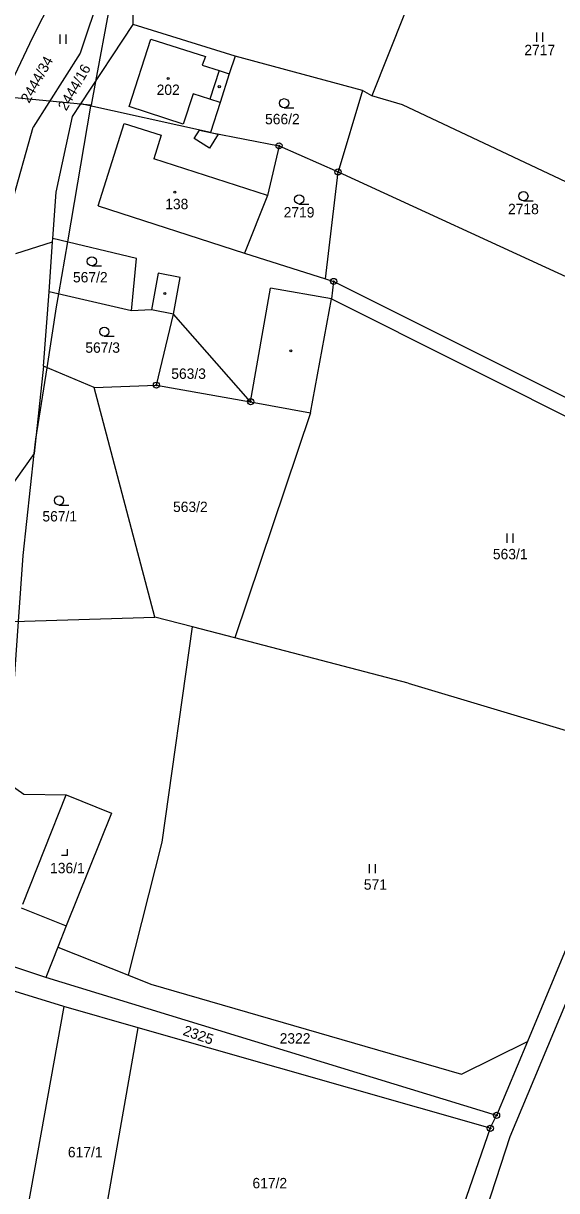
# Model space of a CAD drawing. Extents: x -546762 to -540209, y -1046851 to -1035694.
# Drawn here: x -542556.7 to -542469.1, y -1039468.6 to -1039277.1 of the extents above; entities that cross this region are included whole.
import ezdxf

# ---------------------------------------------------------------- set-up
doc = ezdxf.new("R2010")
doc.units = 0
for name, color, linetype in [('Vrstva 1', 7, 'Continuous'), ('Vrstva 18', 7, 'Continuous'), ('Vrstva 19', 7, 'Continuous'), ('Vrstva 24', 7, 'Continuous'), ('Vrstva 25', 7, 'Continuous'), ('Vrstva 3', 7, 'Continuous'), ('Vrstva 30', 7, 'Continuous'), ('Vrstva 37', 7, 'Continuous'), ('Vrstva 4', 7, 'Continuous'), ('Vrstva 52', 7, 'Continuous')]:
    doc.layers.add(name, color=color, linetype=linetype)

msp = doc.modelspace()

# ---------------------------------------------------------------- linework, layer by layer
at = {"layer": 'Vrstva 1'}
for p, q in [((-542501, -1039288.13), (-542521.91, -1039282.5)), ((-542525.96, -1039295.03), (-542514.67, -1039297.22)), ((-542509.5, -1039341.02), (-542506.07, -1039322.32)), ((-542493.48, -1039385.34), (-542454.3, -1039397.07)), ((-542484.72, -1039449.49), (-542473.9, -1039444.11))]:
    msp.add_line(p, q, dxfattribs=at)
for points in [[(-542538.66, -1039277.31), (-542539.01, -1039251.37)], [(-542486.14, -1039255.6), (-542499.44, -1039289.01)], [(-542555.14, -1039279.37), (-542545.45, -1039260.3)], [(-542543.97, -1039271.83), (-542547.35, -1039282.02)], [(-542547.23, -1039290.34), (-542538.66, -1039277.31)], [(-542521.91, -1039282.5), (-542538.66, -1039277.31)], [(-542569.04, -1039308.59), (-542555.14, -1039279.37)], [(-542547.35, -1039282.02), (-542555.06, -1039294.18)], [(-542521.91, -1039282.5), (-542522.85, -1039285.41)], [(-542522.85, -1039285.41), (-542524.37, -1039290.12)], [(-542501, -1039288.13), (-542505, -1039301.49)], [(-542499.44, -1039289.01), (-542501, -1039288.13)], [(-542524.37, -1039290.12), (-542525.96, -1039295.03)], [(-542494.43, -1039290.51), (-542499.44, -1039289.01)], [(-542548.58, -1039292.39), (-542547.23, -1039290.34)], [(-542525.96, -1039295.03), (-542547.23, -1039290.34)], [(-542460.86, -1039306.3), (-542494.43, -1039290.51)], [(-542551.27, -1039304.84), (-542548.58, -1039292.39)], [(-542558.59, -1039306.85), (-542555.06, -1039294.18)], [(-542514.67, -1039297.22), (-542516.6, -1039305.34)], [(-542514.67, -1039297.22), (-542505, -1039301.49)], [(-542507.04, -1039319.03), (-542505, -1039301.49)], [(-542505, -1039301.49), (-542466.18, -1039319.31)], [(-542551.82, -1039312.41), (-542551.27, -1039304.84)], [(-542516.6, -1039305.34), (-542520.35, -1039314.81)], [(-542557.91, -1039314.9), (-542551.86, -1039312.96)], [(-542552.45, -1039321.14), (-542551.86, -1039312.96)], [(-542551.86, -1039312.96), (-542551.82, -1039312.41)], [(-542538.1, -1039315.69), (-542551.82, -1039312.41)], [(-542520.35, -1039314.81), (-542507.04, -1039319.03)], [(-542538.9, -1039324.26), (-542538.1, -1039315.69)], [(-542507.04, -1039319.03), (-542505.72, -1039319.46)], [(-542505.72, -1039319.46), (-542506.07, -1039322.32)], [(-542461.17, -1039341.73), (-542505.72, -1039319.46)], [(-542553.34, -1039333.38), (-542552.45, -1039321.14)], [(-542538.9, -1039324.26), (-542552.45, -1039321.14)], [(-542506.07, -1039322.32), (-542462.28, -1039344.21)], [(-542535.6, -1039324.14), (-542538.9, -1039324.26)], [(-542531.99, -1039324.82), (-542535.6, -1039324.14)], [(-542534.82, -1039336.47), (-542531.99, -1039324.82)], [(-542519.35, -1039339.2), (-542531.99, -1039324.82)], [(-542553.34, -1039333.38), (-542554.88, -1039347.66)], [(-542545.03, -1039336.86), (-542553.34, -1039333.38)], [(-542545.03, -1039336.86), (-542534.82, -1039336.47)], [(-542535.06, -1039374.51), (-542545.03, -1039336.86)], [(-542534.82, -1039336.47), (-542519.35, -1039339.2)], [(-542519.35, -1039339.2), (-542509.5, -1039341.02)], [(-542509.5, -1039341.02), (-542521.93, -1039377.93)], [(-542554.88, -1039347.66), (-542574.3, -1039374.91)], [(-542572.62, -1039375.69), (-542535.06, -1039374.51)], [(-542528.9, -1039376.11), (-542535.06, -1039374.51)], [(-542533.9, -1039411.45), (-542528.9, -1039376.11)], [(-542521.93, -1039377.93), (-542528.9, -1039376.11)], [(-542493.48, -1039385.34), (-542521.93, -1039377.93)], [(-542454.3, -1039397.07), (-542473.9, -1039444.11)], [(-542476.73, -1039459.71), (-542451.27, -1039398.94)], [(-542562.27, -1039399.57), (-542556.57, -1039403.53)], [(-542556.57, -1039403.53), (-542549.62, -1039403.69)], [(-542549.62, -1039403.69), (-542542.21, -1039406.65)], [(-542542.21, -1039406.65), (-542549.62, -1039425.17)], [(-542539.39, -1039433.27), (-542533.9, -1039411.45)], [(-542557.02, -1039422.21), (-542549.62, -1039425.17)], [(-542549.62, -1039425.17), (-542551, -1039428.63)], [(-542551, -1039428.63), (-542553, -1039433.61)], [(-542551, -1039428.63), (-542539.39, -1039433.27)], [(-542553, -1039433.61), (-542558.25, -1039431.87)], [(-542478.96, -1039456.24), (-542553, -1039433.61)], [(-542539.39, -1039433.27), (-542535.72, -1039434.74)], [(-542550, -1039438.39), (-542558.73, -1039435.72)], [(-542535.72, -1039434.74), (-542484.72, -1039449.49)], [(-542550, -1039438.39), (-542557.58, -1039480.26)], [(-542537.82, -1039441.87), (-542550, -1039438.39)], [(-542545.2, -1039483.83), (-542537.82, -1039441.87)], [(-542479.99, -1039458.36), (-542537.82, -1039441.87)], [(-542473.9, -1039444.11), (-542478.96, -1039456.24)], [(-542479.99, -1039458.36), (-542478.96, -1039456.24)], [(-542479.99, -1039458.36), (-542494.25, -1039499.38)], [(-542490.7, -1039502.54), (-542476.73, -1039459.71)]]:
    msp.add_lwpolyline(points, dxfattribs=at)
at = {"layer": 'Vrstva 24'}
for centre, radius in [((-542514.67, -1039297.22), 0.5), ((-542514.67, -1039297.22), 0.1), ((-542505, -1039301.49), 0.5), ((-542505, -1039301.49), 0.1), ((-542505.72, -1039319.46), 0.5), ((-542505.72, -1039319.46), 0.1), ((-542534.82, -1039336.47), 0.5), ((-542534.82, -1039336.47), 0.1), ((-542519.35, -1039339.2), 0.5), ((-542519.35, -1039339.2), 0.1), ((-542478.96, -1039456.24), 0.5), ((-542478.96, -1039456.24), 0.1), ((-542479.99, -1039458.36), 0.5), ((-542479.99, -1039458.36), 0.1)]:
    msp.add_circle(centre, radius, dxfattribs=at)
at = {"layer": 'Vrstva 25'}
for p, q in [((-542472.37, -1039280.14), (-542472.37, -1039278.64)), ((-542471.37, -1039280.14), (-542471.37, -1039278.64)), ((-542550.65, -1039280.47), (-542550.65, -1039278.97)), ((-542549.65, -1039280.47), (-542549.65, -1039278.97)), ((-542513.84, -1039290.98), (-542512.24, -1039290.98)), ((-542511.38, -1039306.76), (-542509.78, -1039306.76)), ((-542474.55, -1039306.22), (-542472.95, -1039306.22)), ((-542545.42, -1039316.92), (-542543.82, -1039316.92)), ((-542543.38, -1039328.46), (-542541.78, -1039328.46)), ((-542550.81, -1039356.13), (-542549.21, -1039356.13)), ((-542477.23, -1039362.33), (-542477.23, -1039360.83)), ((-542476.23, -1039362.33), (-542476.23, -1039360.83)), ((-542499.84, -1039416.53), (-542499.84, -1039415.03)), ((-542498.84, -1039416.53), (-542498.84, -1039415.03))]:
    msp.add_line(p, q, dxfattribs=at)
msp.add_lwpolyline([(-542550.43, -1039413.56), (-542549.43, -1039413.56), (-542549.43, -1039412.56)], dxfattribs=at)
for centre, radius in [((-542532.9, -1039286.17), 0.175), ((-542524.49, -1039287.51), 0.175), ((-542513.84, -1039290.23), 0.75), ((-542531.8, -1039304.81), 0.175), ((-542511.38, -1039306.01), 0.75), ((-542474.55, -1039305.47), 0.75), ((-542545.42, -1039316.17), 0.75), ((-542533.44, -1039321.45), 0.175), ((-542543.38, -1039327.71), 0.75), ((-542512.75, -1039330.83), 0.175), ((-542550.81, -1039355.38), 0.75)]:
    msp.add_circle(centre, radius, dxfattribs=at)
at = {"layer": 'Vrstva 3'}
for points in [[(-542539.3, -1039290.78), (-542535.72, -1039279.7)], [(-542535.72, -1039279.7), (-542526.78, -1039282.55)], [(-542526.78, -1039282.55), (-542527.28, -1039283.98)], [(-542527.28, -1039283.98), (-542524.52, -1039284.87)], [(-542524.52, -1039284.87), (-542526.04, -1039289.58)], [(-542528.8, -1039288.69), (-542530.4, -1039293.65)], [(-542526.04, -1039289.58), (-542528.8, -1039288.69)], [(-542530.4, -1039293.65), (-542539.3, -1039290.78)], [(-542544.41, -1039307.04), (-542540.13, -1039293.55)], [(-542540.13, -1039293.55), (-542534.03, -1039295.48)], [(-542534.03, -1039295.48), (-542535.26, -1039299.36)], [(-542516.6, -1039305.34), (-542535.26, -1039299.36)], [(-542516.6, -1039305.34), (-542520.35, -1039314.81)], [(-542544.41, -1039307.04), (-542520.35, -1039314.81)]]:
    msp.add_lwpolyline(points, dxfattribs=at)
at = {"layer": 'Vrstva 30'}
for p, q in [((-542528.64, -1039296.02), (-542527.77, -1039294.63)), ((-542527.77, -1039294.63), (-542525.96, -1039295.03)), ((-542524.66, -1039295.28), (-542526.09, -1039297.59)), ((-542525.96, -1039295.03), (-542524.66, -1039295.28)), ((-542526.09, -1039297.59), (-542528.64, -1039296.02))]:
    msp.add_line(p, q, dxfattribs=at)
at = {"layer": 'Vrstva 37'}
for centre in [(-542532.9, -1039286.17), (-542531.8, -1039304.81)]:
    msp.add_circle(centre, 0.175, dxfattribs=at)
at = {"layer": 'Vrstva 4'}
for p, q in [((-542516.6, -1039305.34), (-542535.26, -1039299.36)), ((-542506.07, -1039322.32), (-542516.08, -1039320.55))]:
    msp.add_line(p, q, dxfattribs=at)
for points in [[(-542539.3, -1039290.78), (-542535.72, -1039279.7)], [(-542535.72, -1039279.7), (-542526.78, -1039282.55)], [(-542526.78, -1039282.55), (-542527.28, -1039283.98)], [(-542527.28, -1039283.98), (-542524.52, -1039284.87)], [(-542524.52, -1039284.87), (-542526.04, -1039289.58)], [(-542524.52, -1039284.87), (-542522.85, -1039285.41)], [(-542528.8, -1039288.69), (-542530.4, -1039293.65)], [(-542526.04, -1039289.58), (-542528.8, -1039288.69)], [(-542524.37, -1039290.12), (-542526.04, -1039289.58)], [(-542530.4, -1039293.65), (-542539.3, -1039290.78)], [(-542544.41, -1039307.04), (-542540.13, -1039293.55)], [(-542540.13, -1039293.55), (-542534.03, -1039295.48)], [(-542534.03, -1039295.48), (-542535.26, -1039299.36)], [(-542544.41, -1039307.04), (-542520.35, -1039314.81)], [(-542534.52, -1039318.13), (-542535.6, -1039324.14)], [(-542530.91, -1039318.81), (-542534.52, -1039318.13)], [(-542531.99, -1039324.82), (-542530.91, -1039318.81)], [(-542519.35, -1039339.2), (-542516.08, -1039320.55)], [(-542556.78, -1039421.58), (-542549.62, -1039403.69)]]:
    msp.add_lwpolyline(points, dxfattribs=at)
at = {"layer": 'Vrstva 52'}
for points in [[(-542540.31, -1039262.57), (-542544.81, -1039286.67), (-542545.54, -1039290.55)], [(-542545.54, -1039290.55), (-542546.85, -1039290.42), (-542547.26, -1039290.38), (-542552.34, -1039289.9), (-542559.81, -1039289.18), (-542569.64, -1039288.23)], [(-542559.32, -1039476.62), (-542559.51, -1039441.98), (-542559.57, -1039431.43), (-542559.58, -1039428.76), (-542559.41, -1039421.25), (-542558.98, -1039401.86), (-542558.8, -1039393.98), (-542557.47, -1039375.21), (-542556.71, -1039364.42), (-542554.87, -1039347.66), (-542554.61, -1039345.33), (-542552.78, -1039333.61), (-542551.22, -1039323.62), (-542550.86, -1039321.51), (-542549.39, -1039312.99), (-542545.57, -1039290.71), (-542545.54, -1039290.55)]]:
    msp.add_lwpolyline(points, dxfattribs=at)

# ---------------------------------------------------------------- texts
at = {"layer": 'Vrstva 18'}
for s, p in [('2717', (-542474.4, -1039282.35)), ('566/2', (-542516.98, -1039293.68)), ('2719', (-542513.92, -1039308.97)), ('2718', (-542477.08, -1039308.43)), ('567/2', (-542548.52, -1039319.62)), ('567/3', (-542546.49, -1039331.16)), ('563/3', (-542532.38, -1039335.44)), ('567/1', (-542553.54, -1039358.83)), ('563/2', (-542532.09, -1039357.28)), ('563/1', (-542479.57, -1039365.03)), ('571', (-542500.76, -1039419.23)), ('2322', (-542514.58, -1039444.46)), ('617/1', (-542549.36, -1039463.12)), ('617/2', (-542519.05, -1039468.2))]:
    msp.add_text(s, height=1.7, dxfattribs=at).set_placement(p)
for s, rotation, p in [('2444/34', 60.8197, (-542555.72, -1039290.33)), ('2444/16', 60.09, (-542549.63, -1039291.59)), ('2325', 340.8899, (-542530.59, -1039443.02))]:
    msp.add_text(s, height=1.7, rotation=rotation, dxfattribs=at).set_placement(p)
at = {"layer": 'Vrstva 19'}
for s, p in [('202', (-542534.78, -1039288.87)), ('138', (-542533.37, -1039307.61)), ('136/1', (-542552.28, -1039416.52))]:
    msp.add_text(s, height=1.7, dxfattribs=at).set_placement(p)

doc.saveas('drawing.dxf')
